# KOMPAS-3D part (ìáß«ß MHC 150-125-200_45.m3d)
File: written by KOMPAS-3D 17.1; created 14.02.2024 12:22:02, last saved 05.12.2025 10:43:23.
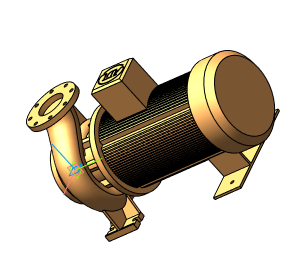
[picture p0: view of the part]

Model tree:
1. Операция без истории:8

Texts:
  ООО АДЛ Групп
